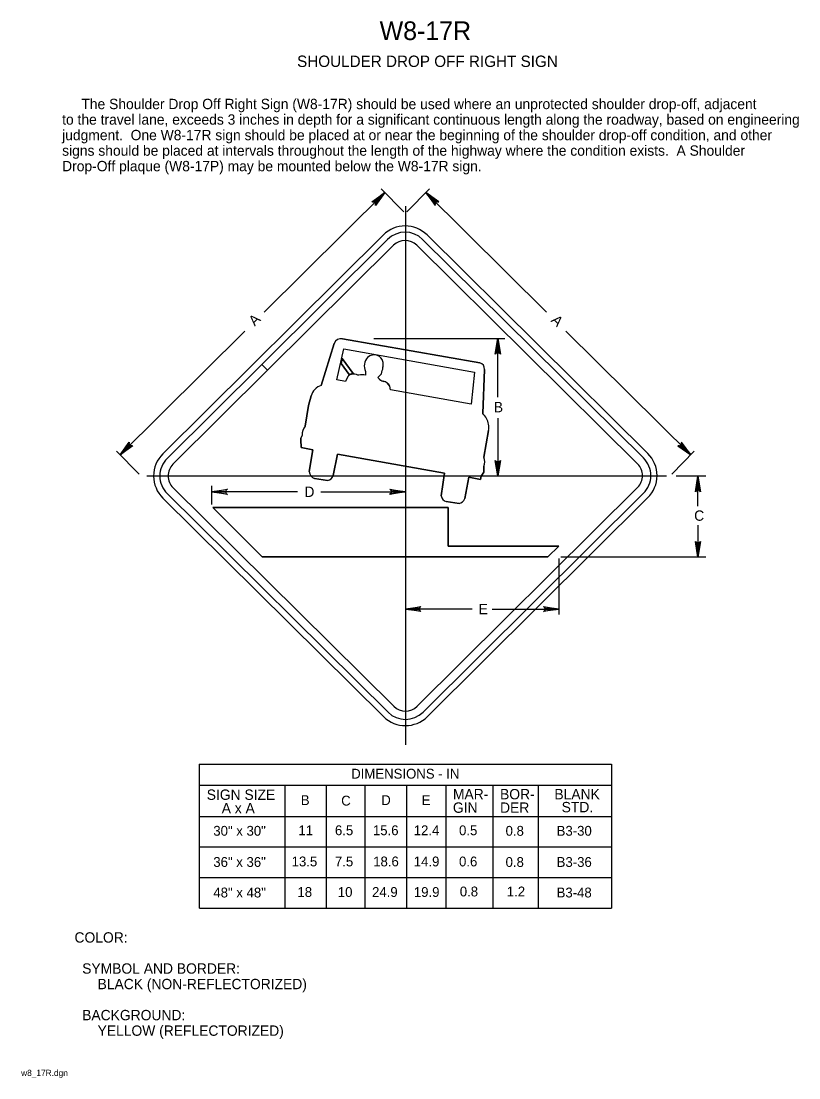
# Model space of a CAD drawing. Extents: x 0.013 to 0.2, y 0.004 to 0.259.
import ezdxf

# ---------------------------------------------------------------- set-up
doc = ezdxf.new("R2010")
doc.units = 0
for name, color, linetype in [('1', 7, 'Continuous'), ('2', 7, 'Continuous'), ('3', 7, 'Continuous')]:
    doc.layers.add(name, color=color, linetype=linetype)

# ---------------------------------------------------------------- blocks, each defined once
blk = doc.blocks.new('RARROW')
at = {"layer": '3'}
for p, q in [((-2.156, 0.28500000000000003), (-2.2665, 0.384625)), ((-2.2665, 0.384625), (0, 0)), ((0, 0), (-2.2665, -0.379125)), ((-2.156, 0.28500000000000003), (-2.075625, 0.12075)), ((0, 0), (-2.156, 0.28500000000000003)), ((-2.14975, -0.2705), (0, 0)), ((-2.075625, 0.12075), (0, 0)), ((0, 0), (-2.074, -0.108)), ((-2.2665, -0.379125), (-2.14975, -0.2705)), ((-2.074, -0.108), (-2.14975, -0.2705))]:
    blk.add_line(p, q, dxfattribs=at)

msp = doc.modelspace()

# ---------------------------------------------------------------- linework, layer by layer
at = {"layer": '1'}
for p, q in [((0.1053605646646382, 0.21437363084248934), (0.1053605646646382, 0.08429732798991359)), ((0.07068008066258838, 0.17616676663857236), (0.10107444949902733, 0.20635984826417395)), ((0.10248395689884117, 0.20494094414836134), (0.07210136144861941, 0.17475955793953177)), ((0.16141532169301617, 0.15217527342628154), (0.10811729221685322, 0.20494559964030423)), ((0.10952445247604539, 0.20636683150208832), (0.16282248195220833, 0.1535965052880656)), ((0.08505390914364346, 0.17112015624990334), (0.08819259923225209, 0.1811998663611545)), ((0.09016226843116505, 0.18239740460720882), (0.1233072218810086, 0.17657475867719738)), ((0.04786371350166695, 0.15350150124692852), (0.07068008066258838, 0.17616676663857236)), ((0.07068008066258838, 0.17616676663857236), (0.07210136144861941, 0.17475955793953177)), ((0.07210136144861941, 0.17475955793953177), (0.07068008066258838, 0.17616676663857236)), ((0.08986157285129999, 0.17643278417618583), (0.09012314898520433, 0.1775714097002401)), ((0.09182068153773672, 0.1737354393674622), (0.08986157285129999, 0.17643278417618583)), ((0.09012314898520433, 0.1775714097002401), (0.09276162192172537, 0.1739698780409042)), ((0.07210136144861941, 0.17475955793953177), (0.049273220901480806, 0.1520825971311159)), ((0.09416162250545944, 0.17356521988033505), (0.09390939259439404, 0.17356521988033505)), ((0.09572639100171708, 0.1745041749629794), (0.09572639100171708, 0.1735498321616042)), ((0.12443120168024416, 0.17494210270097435), (0.12405523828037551, 0.164295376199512)), ((0.09939238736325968, 0.1723319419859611), (0.09874628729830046, 0.17301703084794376)), ((0.08201643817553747, 0.1662603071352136), (0.08261240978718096, 0.16857735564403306)), ((0.10176617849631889, 0.17002603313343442), (0.1015840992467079, 0.17092369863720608)), ((0.10176617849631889, 0.17002603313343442), (0.1015840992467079, 0.17092369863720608)), ((0.08118251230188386, 0.16129817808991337), (0.08201643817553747, 0.1662603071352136)), ((0.12546208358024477, 0.16019208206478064), (0.12433094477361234, 0.1537927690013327)), ((0.08894383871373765, 0.15454455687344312), (0.08795665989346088, 0.14937119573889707)), ((0.11479905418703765, 0.1499010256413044), (0.08894383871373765, 0.15454455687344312)), ((0.042952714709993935, 0.14924478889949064), (0.16834832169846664, 0.14924478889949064)), ((0.08655466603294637, 0.1481437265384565), (0.08345217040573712, 0.14862684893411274)), ((0.11396310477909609, 0.14443843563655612), (0.11479905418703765, 0.1499010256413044)), ((0.04927791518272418, 0.1464023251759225), (0.10257594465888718, 0.0936319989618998)), ((0.10820927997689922, 0.09363665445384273), (0.16142001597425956, 0.14649500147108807)), ((0.10116878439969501, 0.0922107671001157), (0.04787075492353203, 0.14498109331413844)), ((0.16282952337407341, 0.14507609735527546), (0.10961878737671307, 0.0922177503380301)), ((0.11831859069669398, 0.14256405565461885), (0.11521609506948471, 0.14304717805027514))]:
    msp.add_line(p, q, dxfattribs=at)
for points in [[(0.08819259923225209, 0.1811998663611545), (0.08505390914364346, 0.17112015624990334)], [(0.1233072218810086, 0.17657475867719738), (0.09016226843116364, 0.18239740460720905)], [(0.09149367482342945, 0.17323982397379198), (0.0909311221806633, 0.17206023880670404), (0.08881632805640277, 0.17244037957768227), (0.09050398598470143, 0.17990690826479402), (0.12207377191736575, 0.1742813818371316), (0.12120487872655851, 0.1666172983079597), (0.10176617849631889, 0.17002603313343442)], [(0.09149367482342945, 0.17323982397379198), (0.0909311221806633, 0.17206023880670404), (0.08881632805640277, 0.17244037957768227), (0.09050398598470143, 0.17990690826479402), (0.12207377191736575, 0.1742813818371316), (0.12120487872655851, 0.1666172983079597), (0.10176617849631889, 0.17002603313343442)], [(0.0914936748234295, 0.17323982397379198), (0.0909311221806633, 0.17206023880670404), (0.08881632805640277, 0.17244037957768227), (0.09050398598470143, 0.17990690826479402), (0.12207377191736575, 0.1742813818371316), (0.12120487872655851, 0.1666172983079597), (0.10176617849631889, 0.17002603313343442), (0.10158409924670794, 0.17092369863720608)], [(0.09276162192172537, 0.1739698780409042), (0.09012314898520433, 0.1775714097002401), (0.08986157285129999, 0.17643278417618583), (0.09182068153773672, 0.1737354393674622)], [(0.09874628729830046, 0.17301703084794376), (0.09956226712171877, 0.17392630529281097), (0.09972379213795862, 0.17471165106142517), (0.09990759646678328, 0.17504584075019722), (0.09999715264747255, 0.17625142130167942)], [(0.09940409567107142, 0.172349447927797), (0.09939238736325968, 0.1723319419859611), (0.09931660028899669, 0.1724123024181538), (0.09874628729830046, 0.17301703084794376), (0.09956226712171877, 0.17392630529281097), (0.09972379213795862, 0.17471165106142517), (0.09990759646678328, 0.17504584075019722), (0.09996419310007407, 0.1758077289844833), (0.09999715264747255, 0.17625142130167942)], [(0.09416162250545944, 0.17356521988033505), (0.09390939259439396, 0.17356521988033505)], [(0.09572639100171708, 0.17450417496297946), (0.0957263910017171, 0.1735498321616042)], [(0.12405523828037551, 0.16429537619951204), (0.12443120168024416, 0.17494210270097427)], [(0.08261240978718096, 0.16857735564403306), (0.08201643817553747, 0.1662603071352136), (0.08118251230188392, 0.1612981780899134)], [(0.08215930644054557, 0.1503277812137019), (0.08304199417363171, 0.15558969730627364), (0.08020208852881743, 0.15608456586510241), (0.08024105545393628, 0.15684033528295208), (0.08012963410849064, 0.15722047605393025), (0.0800990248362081, 0.15833861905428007), (0.08047140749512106, 0.1590289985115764)], [(0.08047140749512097, 0.15902899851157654), (0.0800990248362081, 0.15833861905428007), (0.08012963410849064, 0.15722047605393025), (0.08024105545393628, 0.15684033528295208), (0.08020208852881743, 0.15608456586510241), (0.08304199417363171, 0.15558969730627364), (0.08215930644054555, 0.1503277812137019)], [(0.12433094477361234, 0.1537927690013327), (0.1254620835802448, 0.16019208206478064)], [(0.08795665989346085, 0.14937119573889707), (0.08894383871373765, 0.15454455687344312), (0.11479905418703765, 0.1499010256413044), (0.11396310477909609, 0.14443843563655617)], [(0.1242559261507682, 0.1515683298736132), (0.1242559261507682, 0.15015706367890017), (0.1236543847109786, 0.14924082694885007), (0.12347615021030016, 0.14836636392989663), (0.12065152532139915, 0.1489420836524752), (0.11972058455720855, 0.14379152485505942)], [(0.11972058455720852, 0.14379152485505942), (0.12065152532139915, 0.1489420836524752), (0.12347615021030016, 0.14836636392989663), (0.1236543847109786, 0.14924082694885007), (0.1242559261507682, 0.15015706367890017), (0.1242559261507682, 0.1515683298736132)], [(0.08345217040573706, 0.1486268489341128), (0.08655466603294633, 0.1481437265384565)], [(0.11521609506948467, 0.1430471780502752), (0.11831859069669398, 0.14256405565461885)], [(0.058848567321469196, 0.1416583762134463), (0.11570815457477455, 0.1416583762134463), (0.11570815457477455, 0.13232612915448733), (0.1423667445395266, 0.13232612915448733), (0.1397099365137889, 0.1296846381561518), (0.07081882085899, 0.12968742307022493), (0.058848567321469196, 0.1416583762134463)], [(0.058848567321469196, 0.1416583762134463), (0.07081882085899, 0.12968742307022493), (0.1397099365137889, 0.1296846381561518), (0.1423667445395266, 0.13232612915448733), (0.11570815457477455, 0.13232612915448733), (0.11570815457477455, 0.1416583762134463), (0.058848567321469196, 0.1416583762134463)]]:
    msp.add_lwpolyline(points, dxfattribs=at)
for centre, radius, start, end in [((0.10530297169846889, 0.20210313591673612), 0.005999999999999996, 45.285051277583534, 134.8096492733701), ((0.10530297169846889, 0.20210313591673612), 0.004000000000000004, 45.285051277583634, 134.80964927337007), ((0.08985490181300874, 0.18068435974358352), 0.0017404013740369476, 79.82782580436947, 162.77050070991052), ((0.08985490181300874, 0.18068435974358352), 0.0017404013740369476, 79.82782580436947, 162.77050070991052), ((0.09853757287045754, 0.1758158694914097), 0.003102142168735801, 138.32612907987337, 205.01370770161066), ((0.09853757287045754, 0.1758158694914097), 0.003102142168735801, 138.32612907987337, 205.01370770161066), ((0.0978411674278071, 0.1760533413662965), 0.0024408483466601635, 70.80672256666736, 131.60533681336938), ((0.0978411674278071, 0.1760533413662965), 0.0024408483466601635, 70.80672256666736, 131.60533681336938), ((0.09779529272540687, 0.1762656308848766), 0.00225827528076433, 16.67265828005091, 67.93559670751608), ((0.09779529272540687, 0.1762656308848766), 0.00225827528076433, 16.67265828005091, 67.93559670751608), ((0.09580555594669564, 0.1763397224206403), 0.004192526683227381, 352.71003464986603, 7.866549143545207), ((0.09580555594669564, 0.1763397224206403), 0.004192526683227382, 358.7931727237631, 7.866549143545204), ((0.12295043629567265, 0.17512591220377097), 0.001492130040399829, 83.90689278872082, 84.01836500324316), ((0.12295043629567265, 0.17512591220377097), 0.001492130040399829, 352.9239894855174, 76.16588841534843), ((0.12295043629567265, 0.17512591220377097), 0.0014921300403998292, 352.9239894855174, 76.16588841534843), ((0.09258814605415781, 0.17244093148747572), 0.0013550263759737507, 98.96289986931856, 143.87299814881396), ((0.09258814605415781, 0.17244093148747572), 0.0013550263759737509, 98.96289986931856, 143.87299814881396), ((0.09258814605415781, 0.17244093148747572), 0.0015049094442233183, 99.04398205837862, 120.66209027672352), ((0.09258814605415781, 0.17244093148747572), 0.0015049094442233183, 99.04398205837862, 120.66209027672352), ((0.0928236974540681, 0.17138644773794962), 0.002584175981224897, 91.37645740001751, 100.57284955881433), ((0.0928236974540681, 0.17138644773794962), 0.002584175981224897, 91.37645740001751, 100.52668517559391), ((0.0928236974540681, 0.17138644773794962), 0.002434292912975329, 63.512650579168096, 100.57284955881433), ((0.0928236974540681, 0.17138644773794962), 0.002434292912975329, 63.512650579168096, 100.57284955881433), ((0.09492468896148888, 0.1715931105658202), 0.002114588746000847, 67.72025503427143, 111.15290361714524), ((0.09492468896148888, 0.1715931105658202), 0.0021145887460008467, 67.72025503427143, 111.15290361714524), ((0.08615754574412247, 0.1676169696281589), 0.003672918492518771, 107.48640344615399, 164.84224255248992), ((0.08615754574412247, 0.1676169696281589), 0.003672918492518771, 107.48640344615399, 164.84224255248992), ((0.10029922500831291, 0.17368782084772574), 0.0016101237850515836, 232.39032141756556, 262.44394256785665), ((0.10029922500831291, 0.17368782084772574), 0.0016101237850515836, 236.22463920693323, 262.44394256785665), ((0.09973935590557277, 0.1701027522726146), 0.0020191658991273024, 23.989986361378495, 82.17651256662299), ((0.09973935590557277, 0.1701027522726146), 0.002019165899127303, 23.9899863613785, 80.07146308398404), ((0.1210369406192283, 0.16104633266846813), 0.004434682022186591, 9.155126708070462, 47.108517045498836), ((0.1210369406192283, 0.16104633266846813), 0.004434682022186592, 9.155126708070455, 47.10851704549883), ((0.08348124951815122, 0.15933179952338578), 0.003025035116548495, 139.45576260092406, 185.74483370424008), ((0.08348124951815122, 0.15933179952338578), 0.003025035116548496, 139.45576260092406, 185.74483370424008), ((0.11988670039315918, 0.160804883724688), 0.005608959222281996, 353.7276818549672, 9.720648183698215), ((0.11988670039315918, 0.160804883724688), 0.005608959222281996, 353.7276818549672, 9.720648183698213), ((0.05209223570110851, 0.1492447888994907), 0.006000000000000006, 134.80964927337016, 225.28505127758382), ((0.12148213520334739, 0.15277535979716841), 0.0030250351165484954, 336.4834763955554, 19.653417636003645), ((0.12148213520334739, 0.15277535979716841), 0.003025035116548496, 336.48347639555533, 19.653417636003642), ((0.15860100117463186, 0.14933280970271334), 0.006000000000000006, 314.8096492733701, 45.285051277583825), ((0.05209223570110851, 0.1492447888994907), 0.004000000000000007, 134.80964927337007, 225.28505127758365), ((0.15860100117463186, 0.14933280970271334), 0.0040000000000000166, 314.8096492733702, 45.28505127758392), ((0.08403535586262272, 0.15041193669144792), 0.0018779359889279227, 182.5684416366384, 251.90786363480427), ((0.08403535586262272, 0.15041193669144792), 0.0018779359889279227, 182.5684416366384, 251.90786363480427), ((0.08618839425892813, 0.14997647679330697), 0.0018689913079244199, 281.3015672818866, 341.1038165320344), ((0.08618839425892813, 0.14997647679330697), 0.0018689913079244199, 281.3015672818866, 341.1038165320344), ((0.11579928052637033, 0.1448322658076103), 0.0018779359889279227, 192.1056143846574, 251.90786363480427), ((0.11579928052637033, 0.1448322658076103), 0.0018779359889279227, 192.1056143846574, 251.90786363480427), ((0.11795231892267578, 0.14439680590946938), 0.0018689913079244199, 281.3015672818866, 341.1038165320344), ((0.11795231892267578, 0.14439680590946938), 0.0018689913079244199, 281.3015672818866, 341.1038165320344), ((0.1053902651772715, 0.09647446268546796), 0.006000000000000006, 225.28505127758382, 314.8096492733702), ((0.1053902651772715, 0.09647446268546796), 0.003999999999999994, 225.28505127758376, 314.8096492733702)]:
    msp.add_arc(centre, radius, start, end, dxfattribs=at)
at = {"layer": '3'}
for p, q in [((0.0712652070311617, 0.18877907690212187), (0.10039481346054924, 0.21765241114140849)), ((0.10497065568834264, 0.21303595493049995), (0.09951484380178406, 0.2185401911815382)), ((0.10575047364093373, 0.21303595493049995), (0.11120628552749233, 0.2185401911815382)), ((0.13945592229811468, 0.18877907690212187), (0.11032631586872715, 0.21765241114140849)), ((0.04680658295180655, 0.154565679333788), (0.10001731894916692, 0.20742402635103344)), ((0.1105798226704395, 0.20743275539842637), (0.16387785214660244, 0.15466242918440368)), ((0.06661774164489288, 0.1841724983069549), (0.0365011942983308, 0.15432090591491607)), ((0.14410338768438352, 0.1841724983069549), (0.17421993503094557, 0.15432090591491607)), ((0.09775841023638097, 0.182427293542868), (0.12938917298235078, 0.182427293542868)), ((0.127668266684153, 0.16828288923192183), (0.127668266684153, 0.18242729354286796)), ((0.127668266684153, 0.16318979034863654), (0.127668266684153, 0.14925197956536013)), ((0.04107703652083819, 0.14970444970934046), (0.035621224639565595, 0.15520868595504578)), ((0.1696440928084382, 0.14970444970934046), (0.1750999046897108, 0.15520868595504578)), ((0.17072446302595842, 0.14924478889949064), (0.1779116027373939, 0.14924478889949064)), ((0.17597973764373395, 0.1419267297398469), (0.17597973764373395, 0.1491900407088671)), ((0.05864325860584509, 0.14236304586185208), (0.05864325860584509, 0.14682891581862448)), ((0.046815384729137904, 0.1439151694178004), (0.1001134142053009, 0.09114484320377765)), ((0.07928965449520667, 0.14542392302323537), (0.05864325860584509, 0.14542392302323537)), ((0.08495980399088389, 0.14542392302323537), (0.1053321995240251, 0.14542392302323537)), ((0.11067591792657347, 0.09115357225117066), (0.16388665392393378, 0.14401191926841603)), ((0.17597973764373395, 0.137335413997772), (0.17597973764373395, 0.12967067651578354)), ((0.14246217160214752, 0.1158187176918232), (0.14246217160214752, 0.12935118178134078)), ((0.14284362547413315, 0.1296846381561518), (0.1779116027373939, 0.1296846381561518)), ((0.12148961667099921, 0.11712335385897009), (0.10535728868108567, 0.11712335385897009)), ((0.1263067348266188, 0.11712335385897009), (0.14246217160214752, 0.11712335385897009)), ((0.05561963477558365, 0.0796723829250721), (0.15510740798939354, 0.0796723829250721)), ((0.05561963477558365, 0.0796723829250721), (0.05561963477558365, 0.044922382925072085)), ((0.15510740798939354, 0.0796723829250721), (0.15510740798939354, 0.044922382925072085)), ((0.15510740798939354, 0.07454633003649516), (0.05561963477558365, 0.07454633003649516)), ((0.07624242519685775, 0.07454633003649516), (0.07624242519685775, 0.044922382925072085)), ((0.0955585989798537, 0.07454633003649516), (0.0955585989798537, 0.044922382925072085)), ((0.12649030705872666, 0.07454633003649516), (0.12649030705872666, 0.044922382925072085)), ((0.13742347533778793, 0.07454633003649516), (0.13742347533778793, 0.044922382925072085)), ((0.05561963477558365, 0.0670473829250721), (0.15510740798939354, 0.0670473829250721)), ((0.055633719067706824, 0.059672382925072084), (0.15510740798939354, 0.059672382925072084)), ((0.055647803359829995, 0.052297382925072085), (0.15510740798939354, 0.052297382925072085)), ((0.055633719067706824, 0.044922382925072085), (0.15510740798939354, 0.044922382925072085))]:
    msp.add_line(p, q, dxfattribs=at)
for points in [[(0.08626963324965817, 0.07454633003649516), (0.08626963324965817, 0.044922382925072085)], [(0.10566226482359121, 0.07454633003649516), (0.10566226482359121, 0.044922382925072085)], [(0.11510535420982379, 0.07454633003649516), (0.11510535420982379, 0.044922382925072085)]]:
    msp.add_lwpolyline(points, dxfattribs=at)
for centre, start, end in [((0.10530297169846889, 0.20210313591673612), 45.285051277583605, 134.80964927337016), ((0.05209223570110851, 0.1492447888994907), 134.80964927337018, 225.28505127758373), ((0.15860100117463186, 0.14933280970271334), 314.8096492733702, 45.28505127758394), ((0.1053902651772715, 0.09647446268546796), 225.2850512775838, 314.80964927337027)]:
    msp.add_arc(centre, 0.0075, start, end, dxfattribs=at)

# ---------------------------------------------------------------- block references
for p, xscale, yscale, rotation in [((0.10039481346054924, 0.21765241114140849), 0.0016545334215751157, 0.0016366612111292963, 44.74685388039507), ((0.11032631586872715, 0.21765241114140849), 0.0016545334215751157, -0.0016366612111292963, 135.25314611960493), ((0.127668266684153, 0.18242729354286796), 0.0016545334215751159, 0.0016366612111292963, 90), ((0.0365011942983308, 0.15432090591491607), 0.001654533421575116, 0.0016366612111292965, -135.25314611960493), ((0.17421993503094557, 0.15432090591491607), 0.001654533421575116, -0.0016366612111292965, -44.74685388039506), ((0.127668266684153, 0.14925197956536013), 0.0016545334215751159, 0.0016366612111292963, -90), ((0.17597973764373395, 0.1491900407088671), 0.0016545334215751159, 0.0016366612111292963, 90), ((0.05864325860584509, 0.14542392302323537), 0.0016545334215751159, 0.0016366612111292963, 180), ((0.17597973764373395, 0.12967067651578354), 0.0016545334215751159, 0.0016366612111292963, -90), ((0.10535728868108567, 0.11712335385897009), 0.0016545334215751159, 0.0016366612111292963, 180)]:
    msp.add_blockref('RARROW', p, dxfattribs=dict(at, xscale=xscale, yscale=yscale, rotation=rotation))
at = {"layer": '3', "xscale": 0.0016545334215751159, "yscale": 0.0016366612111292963}
for p in [(0.1053321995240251, 0.14542392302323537), (0.14246217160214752, 0.11712335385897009)]:
    msp.add_blockref('RARROW', p, dxfattribs=at)

# ---------------------------------------------------------------- texts
at = {"layer": '1'}
for s, height, p in [('W8-17R', 0.0045000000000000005, (0.09914999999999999, 0.2545)), ('SHOULDER DROP OFF RIGHT SIGN', 0.00275025, (0.07922416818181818, 0.248)), ('COLOR:', 0.0024997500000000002, (0.025500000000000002, 0.036577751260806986)), ('  SYMBOL AND BORDER:', 0.0024997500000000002, (0.025500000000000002, 0.029078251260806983)), ('      BLACK (NON-REFLECTORIZED)', 0.0024997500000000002, (0.025500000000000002, 0.02532850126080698)), ('  BACKGROUND:', 0.0024997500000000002, (0.025500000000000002, 0.017829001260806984)), ('      YELLOW (REFLECTORIZED)', 0.0024997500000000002, (0.025500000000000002, 0.014079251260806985)), ('w8_17R.dgn', 0.0015, (0.012625, 0.004375))]:
    msp.add_text(s, height=height, dxfattribs=at).set_placement(p)
at = {"layer": '2'}
for s, p in [('     The Shoulder Drop Off Right Sign (W8-17R) should be used where an unprotected shoulder drop-off, adjacent', (0.02251589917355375, 0.23781558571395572)), ('to the travel lane, exceeds 3 inches in depth for a significant continuous length along the roadway, based on engineering', (0.02251589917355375, 0.23406583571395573)), ('judgment.  One W8-17R sign should be placed at or near the beginning of the shoulder drop-off condition, and other', (0.02251589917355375, 0.23031608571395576)), ('signs should be placed at intervals throughout the length of the highway where the condition exists.  A Shoulder ', (0.02251589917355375, 0.22656633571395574)), ('Drop-Off plaque (W8-17P) may be mounted below the W8-17R sign.', (0.02251589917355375, 0.22281658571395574))]:
    msp.add_text(s, height=0.0024997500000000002, dxfattribs=at).set_placement(p)
at = {"layer": '3'}
for s, height, rotation, p in [('A', 0.0025, 44.746853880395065, (0.06900583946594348, 0.1853058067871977)), ('A', 0.0025, 315.25314611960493, (0.14035725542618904, 0.18665189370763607)), ('B', 0.0024997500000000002, 360, (0.12670433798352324, 0.1646198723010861)), ('D', 0.0025, 360, (0.0809920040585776, 0.14417392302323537)), ('C', 0.0024997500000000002, 360, (0.17506631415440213, 0.13842649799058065)), ('E', 0.0025, 360, (0.12302651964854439, 0.11587335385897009)), ('DIMENSIONS - IN', 0.0023752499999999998, 360, (0.09228785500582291, 0.0761723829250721)), ('E', 0.0023752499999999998, 360, (0.1092986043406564, 0.06979738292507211)), ('15.6', 0.0023752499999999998, 360, (0.09752745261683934, 0.06251029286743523)), ('18.6', 0.0023752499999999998, 360, (0.09759158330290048, 0.05498354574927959)), ('24.9', 0.0023752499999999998, 360, (0.09731806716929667, 0.04760854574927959)), ('0.8', 0.0023752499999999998, 360, (0.11849678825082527, 0.0477335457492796))]:
    msp.add_text(s, height=height, rotation=rotation, dxfattribs=at).set_placement(p)
for s, height, p in [('SIGN SIZE', 0.0024997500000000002, (0.05742012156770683, 0.0710473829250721)), ('B', 0.0023752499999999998, (0.08012681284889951, 0.06979738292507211)), ('C', 0.0023752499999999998, (0.08987011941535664, 0.06966716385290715)), ('D', 0.0023752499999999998, (0.09953417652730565, 0.06979738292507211)), ('MAR-', 0.0024997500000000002, (0.11683816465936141, 0.0711723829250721)), ('BOR-', 0.0024997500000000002, (0.12821316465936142, 0.0711723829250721)), ('BLANK', 0.0024997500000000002, (0.141324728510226, 0.0711723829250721)), ('A x A', 0.0024997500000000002, (0.06103188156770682, 0.0677976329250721)), ('GIN', 0.0024997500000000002, (0.11683816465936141, 0.0679223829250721)), ('DER', 0.0024997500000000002, (0.12821316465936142, 0.0679223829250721)), ('STD.', 0.0024997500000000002, (0.143074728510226, 0.0680473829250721)), ('30" x 30"', 0.0023752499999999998, (0.05900413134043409, 0.06238529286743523)), ('11', 0.0023752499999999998, (0.07955789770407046, 0.06251029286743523)), ('6.5', 0.0023752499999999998, (0.08836201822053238, 0.06251029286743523)), ('12.4', 0.0023752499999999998, (0.10737538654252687, 0.06251029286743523)), ('0.5', 0.0023752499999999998, (0.11831367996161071, 0.06250507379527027)), ('0.8', 0.0023752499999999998, (0.1295478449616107, 0.06238007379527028)), ('B3-30', 0.0023752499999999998, (0.14186984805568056, 0.06238529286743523)), ('36" x 36"', 0.0023752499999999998, (0.05900413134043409, 0.05485854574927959)), ('13.5', 0.0023752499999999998, (0.07791033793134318, 0.05498354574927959)), ('7.5', 0.0023752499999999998, (0.08836201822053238, 0.05498354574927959)), ('14.9', 0.0023752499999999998, (0.1073905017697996, 0.05498354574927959)), ('0.6', 0.0023752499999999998, (0.11831080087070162, 0.05497832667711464)), ('0.8', 0.0023752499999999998, (0.1295478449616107, 0.05485332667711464)), ('B3-36', 0.0023752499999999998, (0.14187488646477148, 0.05485854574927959)), ('48" x 48"', 0.0023752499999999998, (0.05901821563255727, 0.04748354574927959)), ('18', 0.0023752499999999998, (0.07931214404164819, 0.04760854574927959)), ('10', 0.0023752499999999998, (0.08905196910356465, 0.04760854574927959)), ('19.9', 0.0023752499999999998, (0.10740458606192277, 0.04760854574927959)), ('1.2', 0.0023752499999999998, (0.1298422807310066, 0.04773354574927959)), ('B3-48', 0.0023752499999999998, (0.14186193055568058, 0.04748354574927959))]:
    msp.add_text(s, height=height, dxfattribs=at).set_placement(p)

doc.saveas('drawing.dxf')
